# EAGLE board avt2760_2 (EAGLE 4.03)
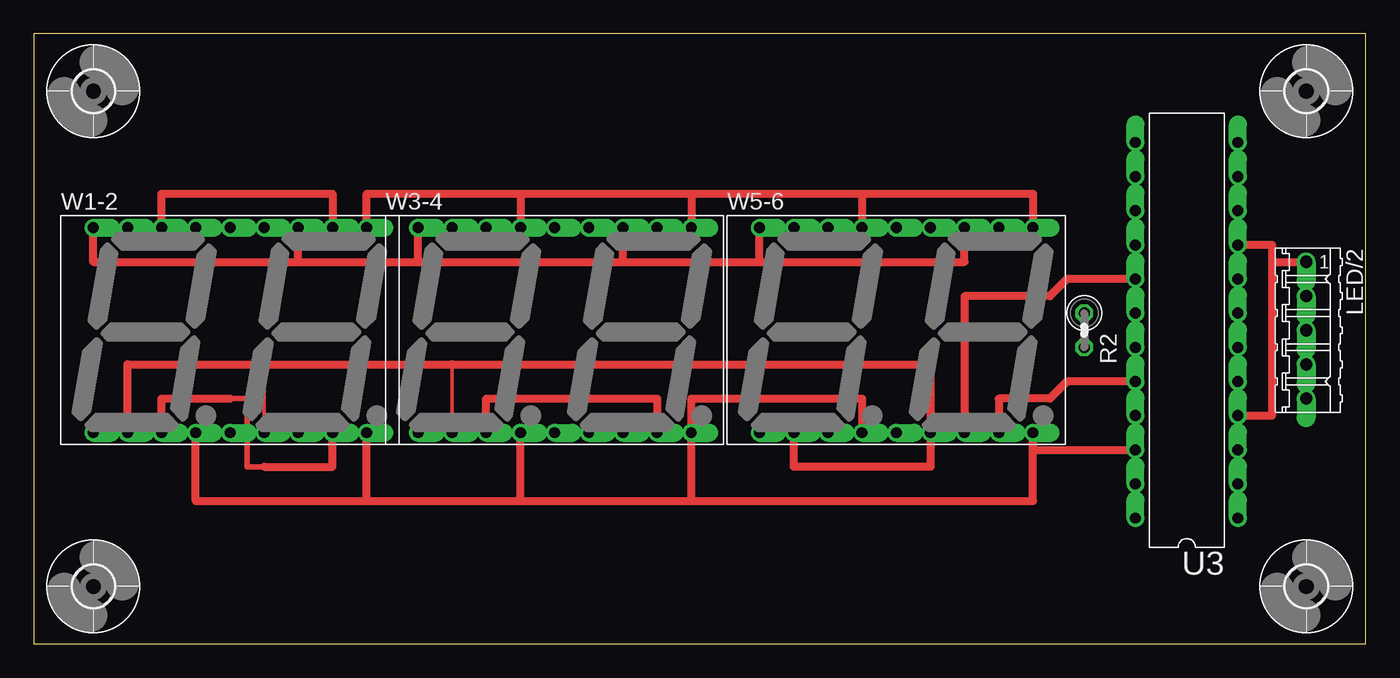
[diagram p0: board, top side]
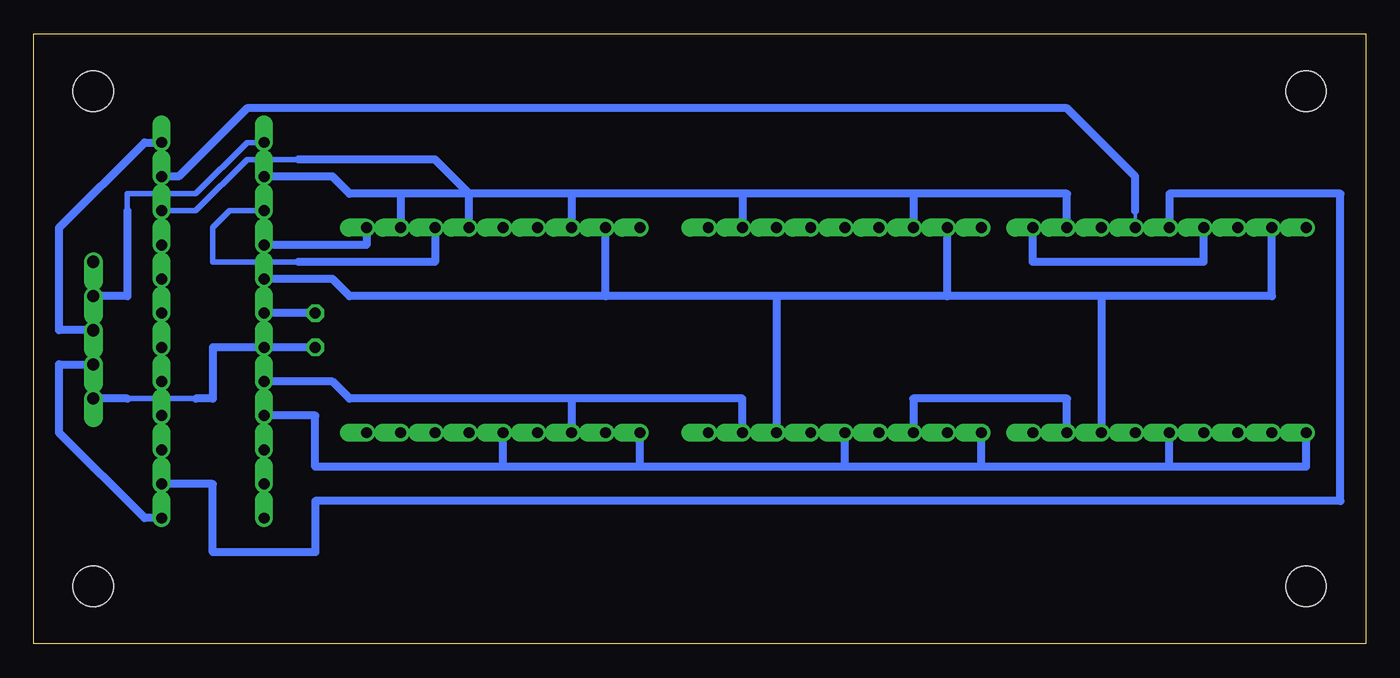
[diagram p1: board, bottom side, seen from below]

Size 99.04 x 45.39 mm. Coordinates in mm from the lower left corner, seen from the top.
Outline: 0,0 99.04,0 99.04,45.39 0,45.39 0,0
Copper layers used: Top, Bottom

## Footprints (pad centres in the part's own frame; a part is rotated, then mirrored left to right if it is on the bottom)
05P = drill 0.914 offset: 1 -5.08,0; 2 -2.54,0; 3 0,0; 4 2.54,0; 5 5.08,0
0207/2V = drill 0.813 octagon: 1 -1.27,0; 2 1.27,0
DIL24-3 = drill 0.813 offset: 1 -13.97,-3.81; 2 -11.43,-3.81; 3 -8.89,-3.81; 4 -6.35,-3.81; 5 -3.81,-3.81; 6 -1.27,-3.81; 7 1.27,-3.81; 8 3.81,-3.81; 9 6.35,-3.81; 10 8.89,-3.81; 11 11.43,-3.81; 12 13.97,-3.81; 13 13.97,3.81; 14 11.43,3.81; 15 8.89,3.81; 16 6.35,3.81; 17 3.81,3.81; 18 1.27,3.81; 19 -1.27,3.81; 20 -3.81,3.81; 21 -6.35,3.81; 22 -8.89,3.81; 23 -11.43,3.81; 24 -13.97,3.81
3,0 = hole 3: 0,0
HDSP-R = drill 0.813 offset: 1 -10.16,-7.62; 2 -7.62,-7.62; 3 -5.08,-7.62; 4 -2.54,-7.62; 5 0,-7.62; 6 2.54,-7.62; 7 5.08,-7.62; 8 7.62,-7.62; 9 10.16,-7.62; 10 10.16,7.62; 11 7.62,7.62; 12 5.08,7.62; 13 2.54,7.62; 14 0,7.62; 15 -2.54,7.62; 16 -5.08,7.62; 17 -7.62,7.62; 18 -10.16,7.62

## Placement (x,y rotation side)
LED/2  [05P]  94.61,23.33 270 top
R2  [0207/2V]  78.1,23.33 270 top
U3  MAX7219  [DIL24-3]  85.72,23.33 90 top
U$1  [3,0]  4.44,4.28 0 top
U$2  [3,0]  4.44,41.11 0 top
U$3  [3,0]  94.61,4.28 0 top
U$4  [3,0]  94.61,41.11 0 top
W1-2  [HDSP-R]  14.6,23.33 0 top
W3-4  [HDSP-R]  38.73,23.33 0 top
W5-6  [HDSP-R]  64.13,23.33 0 top

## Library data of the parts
LED/2 = con-amp-quick
R2 = rcl
U3 = maxim
U$1-U$4 = holes
W1-2 W3-4 W5-6 = display-hp

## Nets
GND: LED/2.1 U3.4 U3.9
N$1: U3.17 W1-2.7 W1-2.17 W3-4.7 W3-4.17 W5-6.7 W5-6.17
N$2: U3.14 W1-2.11 W1-2.16 W3-4.11 W3-4.16 W5-6.11 W5-6.16
N$3: U3.16 W1-2.10 W1-2.15 W3-4.10 W3-4.15 W5-6.10 W5-6.15
N$4: U3.20 W1-2.3 W1-2.8 W3-4.3 W3-4.8 W5-6.3 W5-6.8
N$5: W1-2.2 W1-2.6 W3-4.2 W5-6.2 W5-6.6
N$6: U3.21 W1-2.1 W1-2.5 W3-4.1 W3-4.5 W5-6.1 W5-6.5
N$7: U3.15 W1-2.12 W1-2.18 W3-4.12 W3-4.18 W5-6.12 W5-6.18
N$9: U3.11 W1-2.13
N$10: W3-4.14
N$11: W3-4.13
N$12: W5-6.14
N$13: U3.10 W5-6.13
N$14: U3.22 W1-2.4 W1-2.9 W3-4.4 W3-4.9 W5-6.4 W5-6.9
N$15: LED/2.2 U3.13
N$16: LED/2.3 U3.12
N$17: LED/2.4 U3.1
N$20: R2.1 U3.18
N$31: W3-4.6
N$60: U3.7
N$61: U3.6
N$62: U3.23
N$63: U3.2 W1-2.14
N$64: U3.3
VCC: LED/2.5 R2.2 U3.19

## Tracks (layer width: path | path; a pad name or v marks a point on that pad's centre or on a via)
GND
  Top 0.61: U3.9 92.07,29.68 92.07,28.41 | 92.07,28.41 LED/2.1 | U3.4 92.07,16.98 92.07,28.41
N$1
  Top 0.61: W5-6.7 69.21,25.87 75.56,25.87 76.83,27.14 U3.17
  Bottom 0.61: 56.51,25.87 75.56,25.87 76.83,27.14 U3.17 | 56.51,25.87 W5-6.17 | 31.11,25.87 43.81,25.87 | 43.81,25.87 56.51,25.87 | 31.11,25.87 W3-4.17 | 43.81,25.87 W3-4.7 | 19.68,25.87 6.98,25.87 W1-2.17 | 19.68,25.87 31.11,25.87 | 19.68,25.87 W1-2.7
N$2
  Top 0.61: W1-2.16 9.52,33.49 22.22,33.49 W1-2.11
  Bottom 0.61: 71.75,33.49 W5-6.11 | 71.75,33.49 75.56,33.49 76.83,34.76 U3.14 | W1-2.11 22.22,33.49 33.65,33.49 | 33.65,33.49 W3-4.16 | 46.35,33.49 W3-4.11 | 33.65,33.49 46.35,33.49 | 59.05,33.49 W5-6.16 | 46.35,33.49 59.05,33.49 | 59.05,33.49 71.75,33.49
N$3
  Top 0.61: W5-6.10 74.29,33.49 61.59,33.49 | 61.59,33.49 W5-6.15 | 48.89,33.49 61.59,33.49 | 48.89,33.49 W3-4.10 | 36.19,33.49 48.89,33.49 | 36.19,33.49 W3-4.15 | 36.19,33.49 24.76,33.49 W1-2.10
  Bottom 0.61: W1-2.10 24.76,28.41 12.06,28.41 W1-2.15 | W5-6.10 74.29,29.68 U3.16
N$4
  Top 0.406: 17.14,13.17 15.87,13.17 15.87,18.25 14.6,18.25
  Top 0.61: W5-6.8 71.75,18.25 75.56,18.25 76.83,19.52 U3.20 | W3-4.8 46.35,18.25 33.65,18.25 W3-4.3 | W1-2.8 22.22,13.17 17.14,13.17 | 14.6,18.25 9.52,18.25 W1-2.3
  Bottom 0.61: 59.05,18.25 75.56,18.25 76.83,19.52 U3.20 | 59.05,18.25 W5-6.3 | 59.05,18.25 46.35,18.25 W3-4.8 | W3-4.3 33.65,18.25 22.22,18.25 W1-2.8
N$5
  Top 0.254: 17.14,20.79 W1-2.6 | 31.11,20.79 W3-4.2
  Top 0.61: W1-2.2 6.98,20.79 17.14,20.79 31.11,20.79 66.67,20.79 W5-6.6 66.67,13.17 56.51,13.17 W5-6.2
N$6
  Bottom 0.61: 53.97,13.17 W5-6.1 | 53.97,13.17 64.13,13.17 | 64.13,13.17 W5-6.5 | U3.21 78.1,16.98 78.1,13.17 64.13,13.17 | 38.73,13.17 W3-4.5 | 38.73,13.17 53.97,13.17 | 28.57,13.17 W3-4.1 | 28.57,13.17 38.73,13.17 | 14.6,13.17 W1-2.5 | 14.6,13.17 28.57,13.17 | W1-2.1 4.44,13.17 14.6,13.17
N$7
  Top 0.61: W5-6.12 69.21,28.41 53.97,28.41 | 53.97,28.41 W5-6.18 | 43.81,28.41 53.97,28.41 | 43.81,28.41 W3-4.12 | 28.57,28.41 43.81,28.41 | 28.57,28.41 W3-4.18 | 19.68,28.41 28.57,28.41 | 19.68,28.41 W1-2.12 | 19.68,28.41 4.44,28.41 W1-2.18
  Bottom 0.406: 79.37,28.41 85.72,28.41 85.72,30.95 84.45,32.22 U3.15
  Bottom 0.61: W5-6.12 69.21,28.41 79.37,28.41
N$9
  Bottom 0.254: W1-2.13 17.14,32.22
  Bottom 0.61: 17.14,32.22 17.14,34.76 22.22,39.84 83.18,39.84 88.26,34.76 U3.11
N$13
  Bottom 0.406: 79.37,36.03 83.18,36.03 86.99,32.22 U3.10
  Bottom 0.61: W5-6.13 66.67,33.49 69.21,36.03 79.37,36.03
N$14
  Top 0.61: U3.22 74.29,14.44 W5-6.9 74.29,10.63 48.89,10.63 | W1-2.4 12.06,10.63 24.76,10.63 | 24.76,10.63 W1-2.9 | 24.76,10.63 36.19,10.63 | 36.19,10.63 W3-4.4 | 36.19,10.63 48.89,10.63 | 48.89,10.63 W3-4.9 48.89,18.25 61.59,18.25 W5-6.4
N$15
  Bottom 0.406: U3.13 83.18,37.3 86.99,33.49 92.07,33.49 92.07,32.22
  Bottom 0.61: 92.07,32.22 92.07,25.87 LED/2.2
N$16
  Bottom 0.61: U3.12 90.8,37.3 97.15,30.95 97.15,23.33 LED/2.3
N$17
  Bottom 0.61: U3.1 90.8,9.36 97.15,15.71 97.15,20.79 LED/2.4
N$20
  Bottom 0.61: R2.1 U3.18
N$63
  Bottom 0.61: W1-2.14 14.6,33.49 1.9,33.49 1.9,10.63 78.1,10.63 78.1,6.82 85.72,6.82 85.72,11.9 U3.2
VCC
  Bottom 0.406: 86.99,18.25 92.07,18.25
  Bottom 0.61: R2.2 U3.19 85.72,22.06 85.72,18.25 86.99,18.25 | 92.07,18.25 LED/2.5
